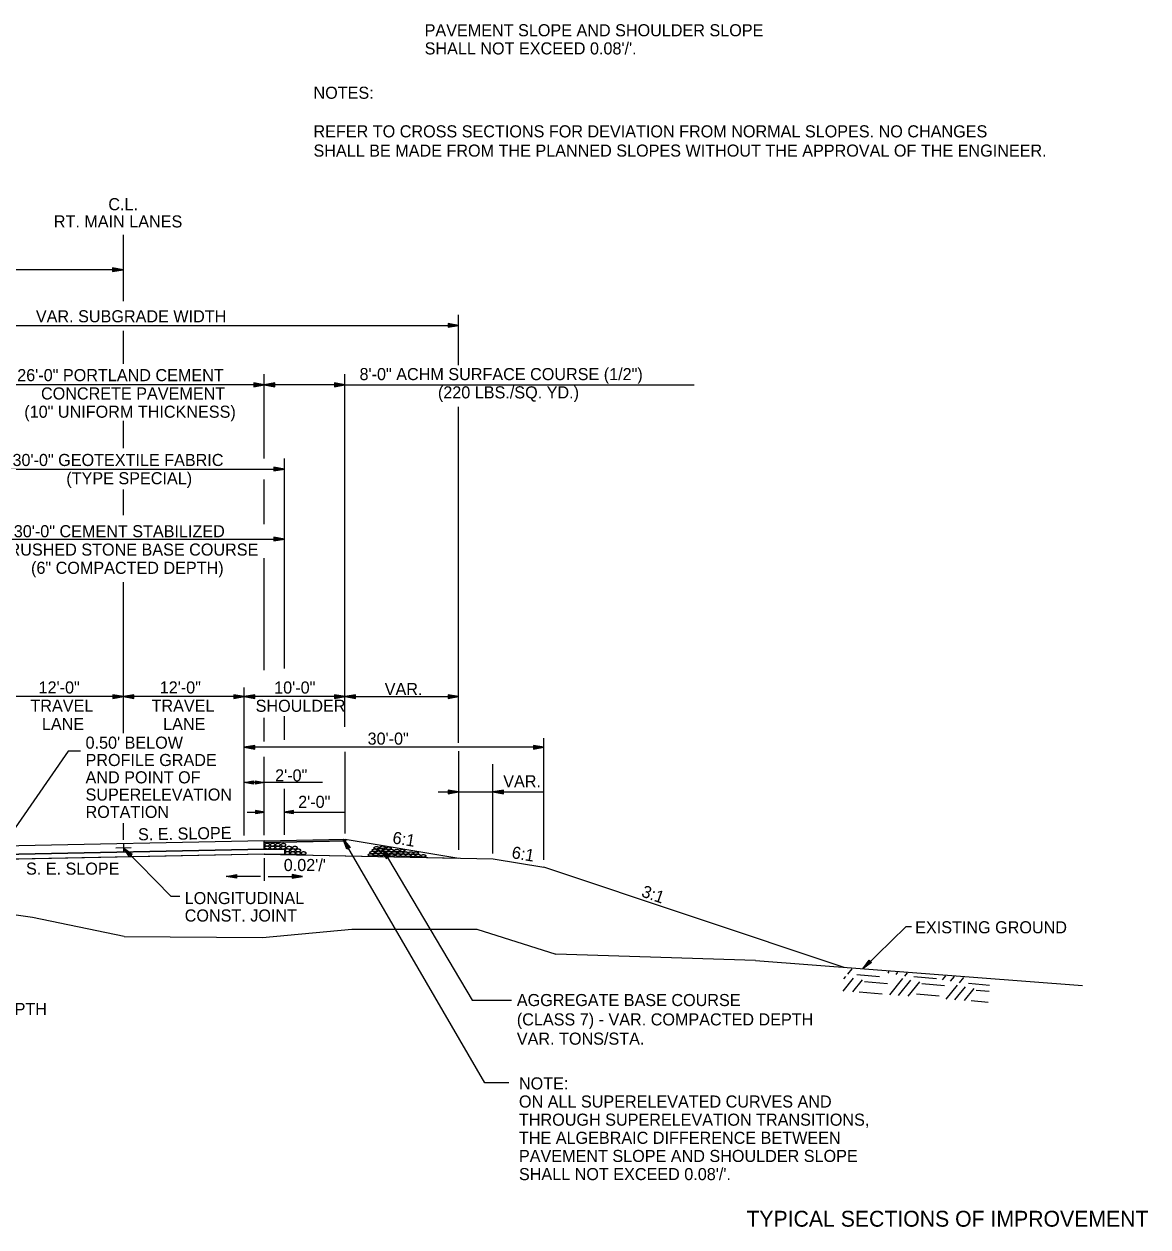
# Model space of a CAD drawing. Extents: x 1734743 to 1735935, y 759845 to 763831.
# Drawn here: x 1735803.1 to 1735914.7, y 760004.7 to 760124.1 of the extents above; entities that cross this region are included whole.
import ezdxf

# ---------------------------------------------------------------- set-up
doc = ezdxf.new("R2010")
doc.units = 0
for name, color, linetype in [('1', 7, 'Continuous'), ('10', 7, 'Continuous'), ('11', 7, 'Continuous'), ('19', 7, 'Continuous'), ('7', 7, 'Continuous'), ('8', 7, 'Continuous'), ('9', 7, 'Continuous'), ('G-ANNO-TEXT', 7, 'Continuous'), ('Level 1', 7, 'Continuous'), ('R_Draft', 7, 'Continuous'), ('R_Prop Surface', 7, 'Continuous')]:
    doc.layers.add(name, color=color, linetype=linetype)

# ---------------------------------------------------------------- blocks, each defined once
blk = doc.blocks.new('TM')
at = {"layer": '8'}
for p, q in [((-120.309, 21.181), (-119.787, -20.829)), ((0, 0), (-120.309, 21.181)), ((-31.382, 2.945), (-120.176, 10.512)), ((-119.787, -20.829), (0, 0)), ((-119.911, -10.826), (-31.307, -3.057))]:
    blk.add_line(p, q, dxfattribs=at)
blk = doc.blocks.new('ROCKS')
at = {"layer": '1'}
blk.add_spline([(0.013, 0.06), (0.053, 0.053), (0.107, 0.033), (0.133, 0.013), (0.133, -0.007), (0.12, -0.033), (0.107, -0.04), (0.073, -0.053), (0.033, -0.067), (0.013, -0.067), (-0.02, -0.06), (-0.06, -0.053), (-0.087, -0.047), (-0.113, -0.02), (-0.113, -0.007), (-0.107, 0.02), (-0.087, 0.033), (-0.067, 0.047), (-0.033, 0.053), (-0.02, 0.06), (0.013, 0.06)], degree=3, dxfattribs=at)

msp = doc.modelspace()

# ---------------------------------------------------------------- linework, layer by layer
at = {"layer": '11'}
for p, q in [((1735803.95, 760035.43), (1735792.76, 760037.09)), ((1735813.05, 760033.56), (1735803.95, 760035.43)), ((1735826.79, 760033.45), (1735835.65, 760034.28)), ((1735835.65, 760034.28), (1735848.06, 760034.28)), ((1735848.06, 760034.28), (1735855.89, 760031.8)), ((1735813.05, 760033.56), (1735826.79, 760033.45)), ((1735875.71, 760031.17), (1735855.89, 760031.8))]:
    msp.add_line(p, q, dxfattribs=at)
msp.add_lwpolyline([(1735875.71, 760031.17), (1735908.15, 760028.68)], dxfattribs=at)
at = {"layer": '19'}
for p, q in [((1735811.9, 760099.91), (1735811.9, 760099.54)), ((1735812.95, 760099.72), (1735811.9, 760099.91)), ((1735812.67, 760099.75), (1735811.9, 760099.81)), ((1735811.9, 760099.54), (1735812.95, 760099.72)), ((1735811.9, 760099.63), (1735812.67, 760099.7)), ((1735846.24, 760090.78), (1735846.24, 760095.24)), ((1735846.24, 760090.26), (1735846.24, 760095.24)), ((1735785.87, 760094.2), (1735846.24, 760094.2)), ((1735845.19, 760094.38), (1735845.19, 760094.01)), ((1735846.24, 760094.2), (1735845.19, 760094.38)), ((1735845.96, 760094.22), (1735845.19, 760094.28)), ((1735845.19, 760094.01), (1735846.24, 760094.2)), ((1735845.19, 760094.1), (1735845.96, 760094.17)), ((1735826.96, 760080.98), (1735826.96, 760089.34)), ((1735834.96, 760054.36), (1735834.96, 760089.34)), ((1735826.96, 760088.29), (1735800.97, 760088.29)), ((1735825.91, 760088.48), (1735825.91, 760088.11)), ((1735826.96, 760088.29), (1735825.91, 760088.48)), ((1735826.68, 760088.32), (1735825.91, 760088.38)), ((1735825.91, 760088.11), (1735826.96, 760088.29)), ((1735825.91, 760088.2), (1735826.68, 760088.27)), ((1735828.01, 760088.48), (1735826.96, 760088.29)), ((1735826.96, 760088.29), (1735828.01, 760088.11)), ((1735834.96, 760088.29), (1735826.96, 760088.29)), ((1735828.01, 760088.38), (1735827.24, 760088.32)), ((1735827.24, 760088.27), (1735828.01, 760088.2)), ((1735828.01, 760088.11), (1735828.01, 760088.48)), ((1735833.91, 760088.48), (1735833.91, 760088.11)), ((1735834.96, 760088.29), (1735833.91, 760088.48)), ((1735834.68, 760088.32), (1735833.91, 760088.38)), ((1735833.91, 760088.11), (1735834.96, 760088.29)), ((1735833.91, 760088.2), (1735834.68, 760088.27)), ((1735834.96, 760088.29), (1735869.62, 760088.29)), ((1735846.24, 760057.4), (1735846.24, 760086.12)), ((1735828.96, 760060.14), (1735828.96, 760080.98)), ((1735798.97, 760079.93), (1735828.96, 760079.93)), ((1735827.91, 760080.12), (1735827.91, 760079.75)), ((1735828.96, 760079.93), (1735827.91, 760080.12)), ((1735828.68, 760079.96), (1735827.91, 760080.02)), ((1735827.91, 760079.75), (1735828.96, 760079.93)), ((1735827.91, 760079.84), (1735828.68, 760079.91)), ((1735826.96, 760074.48), (1735826.96, 760078.89)), ((1735798.97, 760072.99), (1735828.96, 760072.99)), ((1735827.91, 760073.18), (1735827.91, 760072.81)), ((1735828.96, 760072.99), (1735827.91, 760073.18)), ((1735828.68, 760073.02), (1735827.91, 760073.08)), ((1735827.91, 760072.81), (1735828.96, 760072.99)), ((1735827.91, 760072.9), (1735828.68, 760072.97)), ((1735826.96, 760059.98), (1735826.96, 760071.09)), ((1735811.92, 760057.54), (1735811.92, 760057.17)), ((1735812.97, 760057.36), (1735811.92, 760057.54)), ((1735812.69, 760057.38), (1735811.92, 760057.44)), ((1735811.92, 760057.17), (1735812.97, 760057.36)), ((1735811.92, 760057.26), (1735812.69, 760057.33)), ((1735814.02, 760057.54), (1735812.97, 760057.36)), ((1735812.97, 760057.36), (1735814.02, 760057.17)), ((1735814.02, 760057.44), (1735813.25, 760057.38)), ((1735813.25, 760057.33), (1735814.02, 760057.26)), ((1735814.02, 760057.17), (1735814.02, 760057.54)), ((1735823.92, 760057.54), (1735823.92, 760057.17)), ((1735824.97, 760057.36), (1735823.92, 760057.54)), ((1735824.69, 760057.38), (1735823.92, 760057.44)), ((1735823.92, 760057.17), (1735824.97, 760057.36)), ((1735823.92, 760057.26), (1735824.69, 760057.33)), ((1735826.02, 760057.54), (1735824.97, 760057.36)), ((1735824.97, 760057.36), (1735826.02, 760057.17)), ((1735826.02, 760057.44), (1735825.25, 760057.38)), ((1735825.25, 760057.33), (1735826.02, 760057.26)), ((1735826.02, 760057.17), (1735826.02, 760057.54)), ((1735833.92, 760057.54), (1735833.92, 760057.17)), ((1735834.97, 760057.36), (1735833.92, 760057.54)), ((1735834.69, 760057.38), (1735833.92, 760057.44)), ((1735833.92, 760057.17), (1735834.97, 760057.36)), ((1735833.92, 760057.26), (1735834.69, 760057.33)), ((1735836.02, 760057.54), (1735834.97, 760057.36)), ((1735834.97, 760057.36), (1735836.02, 760057.17)), ((1735836.02, 760057.44), (1735835.25, 760057.38)), ((1735835.25, 760057.33), (1735836.02, 760057.26)), ((1735836.02, 760057.17), (1735836.02, 760057.54)), ((1735845.19, 760057.54), (1735845.19, 760057.17)), ((1735846.24, 760057.36), (1735845.19, 760057.54)), ((1735845.96, 760057.38), (1735845.19, 760057.44)), ((1735845.19, 760057.17), (1735846.24, 760057.36)), ((1735845.19, 760057.26), (1735845.96, 760057.33)), ((1735846.24, 760052.76), (1735846.24, 760057.4)), ((1735828.96, 760053.06), (1735828.96, 760055.41)), ((1735826.96, 760052.9), (1735826.96, 760055.25)), ((1735826.02, 760052.52), (1735824.97, 760052.34)), ((1735824.97, 760052.34), (1735826.02, 760052.15)), ((1735826.02, 760052.42), (1735825.25, 760052.36)), ((1735825.25, 760052.31), (1735826.02, 760052.24)), ((1735826.02, 760052.15), (1735826.02, 760052.52)), ((1735846.25, 760042.16), (1735846.25, 760051.96)), ((1735853.66, 760052.52), (1735853.66, 760052.15)), ((1735854.71, 760052.34), (1735853.66, 760052.52)), ((1735854.43, 760052.36), (1735853.66, 760052.42)), ((1735853.66, 760052.15), (1735854.71, 760052.34)), ((1735853.66, 760052.24), (1735854.43, 760052.31)), ((1735826.96, 760043.61), (1735826.96, 760051.38)), ((1735849.65, 760041.78), (1735849.65, 760050.64)), ((1735824.97, 760048.83), (1735825.86, 760048.99)), ((1735825.86, 760048.67), (1735824.97, 760048.83)), ((1735832.72, 760048.83), (1735824.97, 760048.83)), ((1735825.21, 760048.85), (1735825.86, 760048.9)), ((1735825.86, 760048.75), (1735825.21, 760048.81)), ((1735825.86, 760048.99), (1735825.86, 760048.67)), ((1735826.07, 760048.67), (1735826.07, 760048.99)), ((1735826.07, 760048.99), (1735826.97, 760048.83)), ((1735826.07, 760048.91), (1735826.73, 760048.85)), ((1735826.97, 760048.83), (1735826.07, 760048.67)), ((1735826.73, 760048.81), (1735826.07, 760048.75)), ((1735828.96, 760043.65), (1735828.96, 760048.2)), ((1735844.21, 760047.9), (1735854.61, 760047.9)), ((1735845.19, 760048.08), (1735845.19, 760047.71)), ((1735846.24, 760047.9), (1735845.19, 760048.08)), ((1735845.96, 760047.92), (1735845.19, 760047.98)), ((1735845.19, 760047.71), (1735846.24, 760047.9)), ((1735845.19, 760047.8), (1735845.96, 760047.87)), ((1735850.7, 760048.08), (1735849.65, 760047.9)), ((1735849.65, 760047.9), (1735850.7, 760047.71)), ((1735850.7, 760047.98), (1735849.93, 760047.92)), ((1735849.93, 760047.87), (1735850.7, 760047.8)), ((1735850.7, 760047.71), (1735850.7, 760048.08)), ((1735825.25, 760045.9), (1735826.98, 760045.9)), ((1735826.08, 760046.06), (1735826.08, 760045.75)), ((1735826.98, 760045.9), (1735826.08, 760046.06)), ((1735826.74, 760045.92), (1735826.08, 760045.98)), ((1735826.08, 760045.75), (1735826.98, 760045.9)), ((1735826.08, 760045.82), (1735826.74, 760045.88)), ((1735829.87, 760046.06), (1735828.98, 760045.9)), ((1735828.98, 760045.9), (1735834.94, 760045.9)), ((1735828.98, 760045.9), (1735829.87, 760045.75)), ((1735829.87, 760045.99), (1735829.22, 760045.93)), ((1735829.22, 760045.88), (1735829.87, 760045.83)), ((1735829.87, 760045.75), (1735829.87, 760046.06)), ((1735826.96, 760043.05), (1735800.97, 760042.53)), ((1735826.96, 760042.22), (1735800.97, 760041.7)), ((1735813.57, 760041.47), (1735812.97, 760042.34)), ((1735812.97, 760042.34), (1735813.83, 760041.72)), ((1735826.96, 760043.05), (1735834.97, 760043.21)), ((1735826.96, 760042.89), (1735835.05, 760043.05)), ((1735826.96, 760042.22), (1735826.96, 760043.05)), ((1735826.96, 760042.22), (1735828.96, 760042.18)), ((1735828.96, 760042.18), (1735828.96, 760041.68)), ((1735835.16, 760042.21), (1735834.79, 760043.21)), ((1735834.79, 760043.21), (1735835.47, 760042.39)), ((1735835.23, 760042.26), (1735834.9, 760042.96)), ((1735834.95, 760042.98), (1735835.39, 760042.35)), ((1735834.97, 760043.21), (1735846.25, 760041.33)), ((1735835.47, 760042.39), (1735835.16, 760042.21)), ((1735838.66, 760042.3), (1735847.59, 760027.25)), ((1735839.35, 760041.49), (1735838.66, 760042.3)), ((1735838.66, 760042.3), (1735839.04, 760041.3)), ((1735826.96, 760041.72), (1735800.97, 760041.2)), ((1735826.99, 760041.72), (1735800.97, 760041.2)), ((1735813.63, 760041.53), (1735813.14, 760042.13)), ((1735813.18, 760042.16), (1735813.76, 760041.66)), ((1735813.83, 760041.72), (1735813.57, 760041.47)), ((1735826.96, 760041.72), (1735846.25, 760041.33)), ((1735826.96, 760041.72), (1735849.66, 760041.27)), ((1735826.96, 760041.34), (1735826.96, 760039.08)), ((1735838.79, 760042.05), (1735839.12, 760041.36)), ((1735839.28, 760041.45), (1735838.83, 760042.08)), ((1735839.04, 760041.3), (1735839.35, 760041.49)), ((1735849.66, 760041.27), (1735854.71, 760040.42)), ((1735884.5, 760030.49), (1735854.71, 760040.42)), ((1735826.58, 760039.5), (1735823.16, 760039.5)), ((1735827.34, 760039.5), (1735830.76, 760039.5)), ((1735884.86, 760029.82), (1735885.3, 760030.36)), ((1735886.35, 760030.35), (1735886.98, 760031.22)), ((1735887.23, 760030.96), (1735886.35, 760030.35)), ((1735886.54, 760030.56), (1735887.04, 760031.15)), ((1735887.17, 760031.02), (1735886.57, 760030.53)), ((1735886.98, 760031.22), (1735887.23, 760030.96)), ((1735884.41, 760028.13), (1735885.44, 760029.43)), ((1735884.48, 760029.37), (1735884.66, 760029.59)), ((1735885.36, 760028.06), (1735886.32, 760029.27)), ((1735885.75, 760029.78), (1735888, 760029.59)), ((1735886.53, 760029.09), (1735888.79, 760028.9)), ((1735888.87, 760029.93), (1735888.98, 760030.08)), ((1735889.05, 760027.77), (1735890.33, 760029.39)), ((1735889.66, 760029.78), (1735889.84, 760030.01)), ((1735889.9, 760027.7), (1735891.12, 760029.23)), ((1735890.54, 760029.62), (1735890.79, 760029.94)), ((1735890.85, 760027.63), (1735892, 760029.07)), ((1735891.43, 760029.58), (1735893.68, 760029.39)), ((1735894.28, 760029.27), (1735894.58, 760029.64)), ((1735895.07, 760029.11), (1735895.44, 760029.57)), ((1735895.95, 760028.95), (1735896.39, 760029.5)), ((1735886.01, 760028.05), (1735888.26, 760027.86)), ((1735892.21, 760028.89), (1735894.46, 760028.7)), ((1735894.64, 760027.33), (1735895.75, 760028.73)), ((1735895.5, 760027.27), (1735896.54, 760028.57)), ((1735896.45, 760027.19), (1735897.42, 760028.41)), ((1735896.84, 760028.92), (1735898.94, 760028.74)), ((1735897.62, 760028.23), (1735898.89, 760028.12)), ((1735847.59, 760027.25), (1735851.5, 760027.25)), ((1735891.68, 760027.85), (1735893.93, 760027.66)), ((1735897.1, 760027.19), (1735898.81, 760027.04))]:
    msp.add_line(p, q, dxfattribs=at)
for points in [[(1735798.97, 760041.16), (1735798.97, 760041.66), (1735826.96, 760042.22), (1735828.96, 760042.18), (1735828.96, 760041.68), (1735828.96, 760041.68), (1735828.96, 760041.68), (1735826.96, 760041.72), (1735798.97, 760041.16)], [(1735818.57, 760037.54), (1735817.7, 760037.54), (1735812.97, 760042.34)], [(1735835.05, 760043.05), (1735826.96, 760042.89), (1735826.96, 760042.89), (1735826.96, 760043.05), (1735826.96, 760043.05), (1735826.96, 760043.05), (1735834.97, 760043.21), (1735834.97, 760043.21), (1735834.97, 760043.21), (1735835.05, 760043.05), (1735835.05, 760043.05), (1735835.05, 760043.05)], [(1735891.18, 760034.53), (1735890.61, 760034.53), (1735886.35, 760030.35)]]:
    msp.add_lwpolyline(points, dxfattribs=at)
msp.add_lwpolyline([(1735826.96, 760043.05), (1735800.97, 760042.53), (1735800.97, 760041.7), (1735826.96, 760042.22)], close=True, dxfattribs=at)
at = {"layer": '7'}
for p, q in [((1735812.97, 760096.61), (1735812.97, 760103.17)), ((1735812.97, 760090.37), (1735812.97, 760093.65)), ((1735812.97, 760082), (1735812.97, 760084.72)), ((1735812.97, 760075.35), (1735812.97, 760077.91)), ((1735812.97, 760053.73), (1735812.97, 760068.7)), ((1735812.97, 760043.16), (1735812.97, 760044.8))]:
    msp.add_line(p, q, dxfattribs=at)
at = {"layer": '9'}
for p, q in [((1735812.97, 760099.72), (1735760.97, 760099.72)), ((1735824.97, 760043.57), (1735824.97, 760058.26)), ((1735812.97, 760057.36), (1735800.97, 760057.36)), ((1735824.97, 760057.36), (1735812.97, 760057.36)), ((1735834.97, 760057.36), (1735824.97, 760057.36)), ((1735834.97, 760057.36), (1735846.24, 760057.36)), ((1735854.71, 760052.34), (1735854.71, 760053.24)), ((1735854.71, 760052.34), (1735824.97, 760052.34)), ((1735834.97, 760046.82), (1735834.97, 760051.89)), ((1735854.71, 760041.15), (1735854.71, 760052.34)), ((1735834.97, 760043.76), (1735834.97, 760046.82)), ((1735848.85, 760019.03), (1735834.79, 760043.21))]:
    msp.add_line(p, q, dxfattribs=at)
for points in [[(1735808.71, 760051.96), (1735807.48, 760051.96), (1735800.97, 760042.53)], [(1735851.21, 760019.03), (1735848.85, 760019.03)]]:
    msp.add_lwpolyline(points, dxfattribs=at)
at = {"layer": 'R_Draft'}
for p, q in [((1735813.74, 760042.36), (1735812.22, 760042.33)), ((1735812.97, 760042.72), (1735812.97, 760041.97))]:
    msp.add_line(p, q, dxfattribs=at)
at = {"layer": 'R_Prop Surface'}
msp.add_line((1735834.97, 760043.21), (1735835.05, 760043.05), dxfattribs=at)

# ---------------------------------------------------------------- block references
at = {"layer": '19', "xscale": 0.008761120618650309}
for p, yscale, rotation in [((1735823.16, 760039.5), -0.008761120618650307, -179.20057588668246), ((1735830.76, 760039.5), 0.008761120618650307, -0.7994241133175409)]:
    msp.add_blockref('TM', p, dxfattribs=dict(at, yscale=yscale, rotation=rotation))
at = {"layer": 'Level 1', "xscale": 2.011654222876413}
for p, yscale, rotation in [((1735827.22, 760042.39), 2.011654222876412, 1.33680650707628), ((1735827.23, 760042.67), 2.011654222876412, 1.33680650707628), ((1735827.76, 760042.38), 2.011654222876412, 1.33680650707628), ((1735827.77, 760042.66), 2.011654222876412, 1.33680650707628), ((1735828.29, 760042.38), 2.011654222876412, 1.33680650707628), ((1735828.29, 760042.66), 2.011654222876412, 1.33680650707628), ((1735828.84, 760042.65), 2.011654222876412, 1.33680650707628), ((1735828.83, 760042.37), 2.011654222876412, 1.33680650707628), ((1735829.24, 760042.12), 2.011654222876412, 1.33680650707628), ((1735829.4, 760042.37), 2.011654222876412, 1.33680650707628), ((1735829.79, 760042.11), 2.011654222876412, 1.33680650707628), ((1735829.97, 760042.37), 2.011654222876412, 1.33680650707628), ((1735830.31, 760042.11), 2.011654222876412, 1.33680650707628), ((1735837.94, 760042.12), -2.011654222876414, 178.00441377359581), ((1735838.12, 760042.36), -2.011654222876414, 178.00441377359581), ((1735838.52, 760042.16), -2.011654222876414, 178.00441377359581), ((1735838.72, 760042.42), -2.011654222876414, 178.00441377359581), ((1735839.04, 760042.12), -2.011654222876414, 178.00441377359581), ((1735839.32, 760042.32), -2.011654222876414, 178.00441377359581), ((1735839.59, 760042.09), -2.011654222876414, 178.00441377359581), ((1735840.14, 760042.08), -2.011654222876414, 178.00441377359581), ((1735840.68, 760042.09), -2.011654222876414, 178.00441377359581), ((1735829.24, 760041.84), 2.011654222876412, 1.33680650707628), ((1735829.78, 760041.83), 2.011654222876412, 1.33680650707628), ((1735830.3, 760041.83), 2.011654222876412, 1.33680650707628), ((1735830.84, 760041.83), 2.011654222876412, 1.33680650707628), ((1735837.53, 760041.65), -2.011654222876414, 178.00441377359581), ((1735837.71, 760041.89), -2.011654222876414, 178.00441377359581), ((1735838.03, 760041.68), -2.011654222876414, 178.00441377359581), ((1735838.29, 760041.92), -2.011654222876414, 178.00441377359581), ((1735838.56, 760041.68), -2.011654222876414, 178.00441377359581), ((1735838.82, 760041.9), -2.011654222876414, 178.00441377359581), ((1735839.09, 760041.64), -2.011654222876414, 178.00441377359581), ((1735839.33, 760041.87), -2.011654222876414, 178.00441377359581), ((1735839.65, 760041.64), -2.011654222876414, 178.00441377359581), ((1735839.91, 760041.85), -2.011654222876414, 178.00441377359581), ((1735840.26, 760041.64), -2.011654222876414, 178.00441377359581), ((1735840.52, 760041.85), -2.011654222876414, 178.00441377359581), ((1735840.75, 760041.62), -2.011654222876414, 178.00441377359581), ((1735841.01, 760041.84), -2.011654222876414, 178.00441377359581), ((1735841.25, 760041.62), -2.011654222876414, 178.00441377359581), ((1735841.52, 760041.84), -2.011654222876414, 178.00441377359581), ((1735841.75, 760041.6), -2.011654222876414, 178.00441377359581), ((1735842.03, 760041.84), -2.011654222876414, 178.00441377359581), ((1735842.24, 760041.59), -2.011654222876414, 178.00441377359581), ((1735842.77, 760041.56), -2.011654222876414, 178.00441377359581)]:
    msp.add_blockref('ROCKS', p, dxfattribs=dict(at, yscale=yscale, rotation=rotation))

# ---------------------------------------------------------------- texts
at = {"layer": '1'}
for s, p in [('NOTES:', (1735831.84, 760116.68)), ('REFER TO CROSS SECTIONS FOR DEVIATION FROM NORMAL SLOPES. NO CHANGES', (1735831.84, 760112.85)), ('SHALL BE MADE FROM THE PLANNED SLOPES WITHOUT THE APPROVAL OF THE ENGINEER.', (1735831.84, 760110.94))]:
    msp.add_text(s, height=1.2, dxfattribs=at).set_placement(p)
at = {"layer": '10'}
for s, p in [('PAVEMENT SLOPE AND SHOULDER SLOPE', (1735842.87, 760122.88)), ("SHALL NOT EXCEED 0.08'/'.", (1735842.87, 760121.08)), ('10\'-0"', (1735827.94, 760057.66)), ('VAR.', (1735838.91, 760057.51)), ('SHOULDER', (1735826.1, 760055.85)), ("0.50' BELOW", (1735809.22, 760052.19)), ('30\'-0"', (1735837.21, 760052.59)), ('PROFILE GRADE', (1735809.22, 760050.47)), ('AND POINT OF', (1735809.22, 760048.75)), ('SUPERELEVATION', (1735809.22, 760047.04)), ('ROTATION  ', (1735809.22, 760045.32)), ('S. E. SLOPE', (1735803.31, 760039.69))]:
    msp.add_text(s, height=1.2, dxfattribs=at).set_placement(p)
for s, rotation, p in [('S. E. SLOPE', 0.9769, (1735814.44, 760043.09)), ('6:1', 350.5489, (1735839.62, 760042.81)), ('6:1', 350.5489, (1735851.45, 760041.34)), ('3:1', 340.4943, (1735864.3, 760037.55))]:
    msp.add_text(s, height=1.2, rotation=rotation, dxfattribs=at).set_placement(p)
at = {"layer": '19'}
for s, p in [('C.L.', (1735811.48, 760105.62)), ('RT. MAIN LANES', (1735806.07, 760103.91)), ('VAR. SUBGRADE WIDTH', (1735804.29, 760094.5)), ('8\'-0" ACHM SURFACE COURSE (1/2")', (1735836.41, 760088.76)), ('26\'-0" PORTLAND CEMENT', (1735802.44, 760088.66)), ('CONCRETE PAVEMENT', (1735804.8, 760086.84)), ('(220 LBS./SQ. YD.)', (1735844.19, 760086.95)), ('(10" UNIFORM THICKNESS)', (1735803.14, 760085.03)), ('30\'-0" GEOTEXTILE FABRIC', (1735801.97, 760080.24)), ('(TYPE SPECIAL)', (1735807.31, 760078.43)), ('30\'-0" CEMENT STABILIZED ', (1735802.1, 760073.17)), ('CRUSHED STONE BASE COURSE', (1735800.42, 760071.35)), ('(6" COMPACTED DEPTH)', (1735803.81, 760069.54)), ('12\'-0"', (1735804.56, 760057.67)), ('12\'-0"', (1735816.58, 760057.67)), ('TRAVEL', (1735803.75, 760055.86)), ('TRAVEL', (1735815.77, 760055.86)), ('LANE', (1735804.89, 760054.05)), ('LANE', (1735816.92, 760054.05)), ('2\'-0"', (1735828.03, 760048.94)), ('VAR.', (1735850.67, 760048.36)), ('2\'-0"', (1735830.32, 760046.32)), ("0.02'/'", (1735828.89, 760040.05)), ('LONGITUDINAL', (1735819.06, 760036.77)), ('CONST. JOINT', (1735819.06, 760035.04)), ('EXISTING GROUND', (1735891.55, 760033.87)), ('NOTE:', (1735852.23, 760018.38)), ('ON ALL SUPERELEVATED CURVES AND', (1735852.23, 760016.58)), ('THROUGH SUPERELEVATION TRANSITIONS,', (1735852.23, 760014.78)), ('THE ALGEBRAIC DIFFERENCE BETWEEN', (1735852.23, 760012.98)), ('PAVEMENT SLOPE AND SHOULDER SLOPE', (1735852.23, 760011.18)), ("SHALL NOT EXCEED 0.08'/'.", (1735852.23, 760009.38))]:
    msp.add_text(s, height=1.2, dxfattribs=at).set_placement(p)
for s, p in [('AGGREGATE BASE COURSE', (1735852.02, 760026.65)), ('(CLASS 7) - VAR. COMPACTED DEPTH', (1735775.97, 760025.76)), ('(CLASS 7) - VAR. COMPACTED DEPTH', (1735852.02, 760024.73)), ('VAR. TONS/STA.', (1735852.02, 760022.82))]:
    msp.add_text(s, height=1.2, rotation=360, dxfattribs=at).set_placement(p)
at = {"layer": 'G-ANNO-TEXT'}
msp.add_text('TYPICAL SECTIONS OF IMPROVEMENT', height=1.575, dxfattribs=at).set_placement((1735874.8, 760004.76))

doc.saveas('drawing.dxf')
